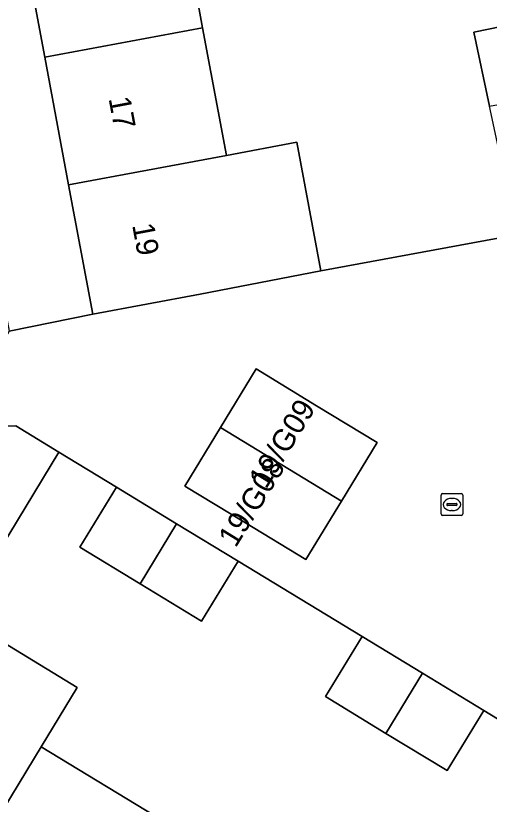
# Model space of a CAD drawing. Extents: x 158352 to 159489, y 383828 to 384603.
# Drawn here: x 158825.42 to 158847.09, y 383963.32 to 383999.38 of the extents above; entities that cross this region are included whole.
import ezdxf

# ---------------------------------------------------------------- set-up
doc = ezdxf.new("R2010")
doc.units = 0
for name, color, linetype in [('IMGEO_Erf', 7, 'Continuous'), ('IMGEO_Kolk', 7, 'Continuous'), ('IMGEO_Pand', 7, 'Continuous'), ('IMGEO_Pand_nummerreeks', 7, 'Continuous'), ('IMGEO_Rijbaan_lokaal_open', 7, 'Continuous')]:
    doc.layers.add(name, color=color, linetype=linetype)

msp = doc.modelspace()

# ---------------------------------------------------------------- linework, layer by layer
at = {"layer": 'IMGEO_Erf'}
for points in [[(158822.303, 384000), (158825.129, 383984.951), (158828.945, 383985.73), (158827.842, 383991.649), (158826.753, 383997.491), (158826.285, 384000)], [(158833.757, 384000), (158833.974, 383998.837), (158835.061, 383992.995), (158838.291, 383993.597), (158839.385, 383987.718), (158851.565, 383989.958), (158851.212, 383991.707), (158848.003, 383991.06), (158847.11, 383995.242), (158846.386, 383998.637), (158849.595, 383999.284), (158850.329, 383995.842), (158863.244, 383988.747), (158874.013, 383982.831), (158882.083, 383989.971)], [(158849.616, 383965.92), (158846.84, 383967.608), (158845.169, 383964.859), (158842.366, 383966.562), (158839.602, 383968.242), (158841.273, 383970.991), (158835.6, 383974.441), (158833.929, 383971.692), (158831.114, 383973.403), (158828.362, 383975.075), (158830.033, 383977.824), (158827.393, 383979.426), (158822.843, 383971.94), (158828.233, 383968.664), (158826.585, 383965.952), (158832.219, 383962.527), (158837.825, 383959.119), (158843.416, 383955.721), (158848.864, 383952.409)]]:
    msp.add_lwpolyline(points, dxfattribs=at)
at = {"layer": 'IMGEO_Kolk'}
for p, q in [((158844.886, 383976.603), (158844.886, 383977.455)), ((158844.961, 383977.529), (158845.813, 383977.529)), ((158845.887, 383977.455), (158845.887, 383976.603)), ((158845.188, 383977.072), (158845.586, 383977.072)), ((158845.374, 383977.309), (158845.399, 383977.309)), ((158845.145, 383977.023), (158845.145, 383977.035)), ((158845.583, 383976.986), (158845.185, 383976.986)), ((158845.397, 383976.749), (158845.372, 383976.749)), ((158845.629, 383977.035), (158845.629, 383977.023)), ((158845.813, 383976.529), (158844.961, 383976.529))]:
    msp.add_line(p, q, dxfattribs=at)
for points in [[(158844.886, 383976.603), (158844.886, 383977.455)], [(158844.961, 383977.529), (158845.813, 383977.529)], [(158845.887, 383977.455), (158845.887, 383976.603)], [(158845.813, 383976.529), (158844.961, 383976.529)]]:
    msp.add_lwpolyline(points, dxfattribs=at)
for centre, radius, start, end in [((158844.963, 383977.453), 0.0765, 91.552, 178.448), ((158844.963, 383977.453), 0.0765, 91.552, 178.448), ((158845.811, 383977.453), 0.0765, 1.552, 88.448), ((158845.811, 383977.453), 0.0765, 1.552, 88.448), ((158845.185, 383977.032), 0.0403, 85.8775, 175.7526), ((158845.59, 383977.034), 0.0386, 1.7309, 96.639), ((158845.182, 383977.022), 0.0366, 178.938, 274.7102), ((158845.586, 383977.029), 0.043, 264.8664, 352.4533), ((158844.963, 383976.605), 0.0765, 181.552, 268.448), ((158844.963, 383976.605), 0.0765, 181.552, 268.448), ((158845.811, 383976.605), 0.0765, 271.552, 358.448), ((158845.811, 383976.605), 0.0765, 271.552, 358.448)]:
    msp.add_arc(centre, radius, start, end, dxfattribs=at)
for centre, major_axis, ratio, start_param, end_param in [((158845.373, 383977.029), (-0.387, 0.002), 0.722429, 4.712389, 7.853982), ((158845.398, 383977.029), (-0.39, 0.002), 0.717154, 1.570796, 4.712389)]:
    msp.add_ellipse(centre, major_axis=major_axis, ratio=ratio, start_param=start_param, end_param=end_param, dxfattribs=at)
at = {"layer": 'IMGEO_Pand'}
for points in [[(158826.753, 383997.491), (158833.974, 383998.837), (158833.757, 384000), (158832.942, 384004.38), (158832.415, 384004.282), (158825.719, 384003.034), (158826.285, 384000)], [(158850.329, 383995.842), (158849.595, 383999.284), (158846.386, 383998.637), (158847.11, 383995.242)], [(158826.753, 383997.491), (158827.842, 383991.649), (158835.061, 383992.995), (158833.974, 383998.837)], [(158835.061, 383992.995), (158827.842, 383991.649), (158828.945, 383985.73), (158833.861, 383986.646), (158836.159, 383987.092), (158839.385, 383987.718), (158838.291, 383993.597)], [(158834.796, 383980.553), (158840.33, 383977.189), (158841.958, 383979.866), (158839.192, 383981.548), (158836.423, 383983.231)], [(158827.393, 383979.426), (158825.424, 383980.625), (158823.318, 383980.566), (158814.431, 383965.842), (158817.576, 383963.931), (158816.018, 383961.367), (158821.699, 383957.914), (158826.585, 383965.952), (158828.233, 383968.664), (158822.843, 383971.94)], [(158834.796, 383980.553), (158833.168, 383977.875), (158835.935, 383976.193), (158838.702, 383974.511), (158840.33, 383977.189)], [(158832.785, 383976.152), (158830.033, 383977.824), (158828.362, 383975.075), (158831.114, 383973.403)], [(158832.785, 383976.152), (158831.114, 383973.403), (158833.929, 383971.692), (158835.6, 383974.441)], [(158842.366, 383966.562), (158844.042, 383969.309), (158841.273, 383970.991), (158839.602, 383968.242)], [(158842.366, 383966.562), (158845.169, 383964.859), (158846.84, 383967.608), (158844.042, 383969.309)], [(158827.264, 383954.531), (158832.219, 383962.527), (158826.585, 383965.952), (158821.699, 383957.914)]]:
    msp.add_lwpolyline(points, close=True, dxfattribs=at)
at = {"layer": 'IMGEO_Rijbaan_lokaal_open'}
msp.add_lwpolyline([(158851.565, 383989.958), (158839.385, 383987.718), (158836.159, 383987.092), (158833.861, 383986.646), (158828.945, 383985.73), (158825.129, 383984.951), (158824.65, 383984.127), (158822.729, 383980.822), (158814.158, 383966.008), (158814.431, 383965.842), (158823.318, 383980.566), (158825.424, 383980.625), (158827.393, 383979.426), (158830.033, 383977.824), (158832.785, 383976.152), (158835.6, 383974.441), (158841.273, 383970.991), (158844.042, 383969.309), (158846.84, 383967.608), (158849.616, 383965.92)], dxfattribs=at)
msp.add_lwpolyline([(158840.33, 383977.189), (158838.702, 383974.511), (158835.935, 383976.193), (158833.168, 383977.875), (158834.796, 383980.553), (158836.423, 383983.231), (158839.192, 383981.548), (158841.958, 383979.866)], close=True, dxfattribs=at)

# ---------------------------------------------------------------- texts
at = {"layer": 'IMGEO_Pand_nummerreeks'}
for s, rotation, p in [('17', 280.5599, (158829.668, 383995.597)), ('19', 280.5594, (158830.747, 383989.809)), ('19/G09', 58.3989, (158836.877, 383977.697)), ('19/G08', 58.3989, (158835.486, 383975.017))]:
    msp.add_text(s, height=1, rotation=rotation, dxfattribs=at).set_placement(p)

doc.saveas('drawing.dxf')
